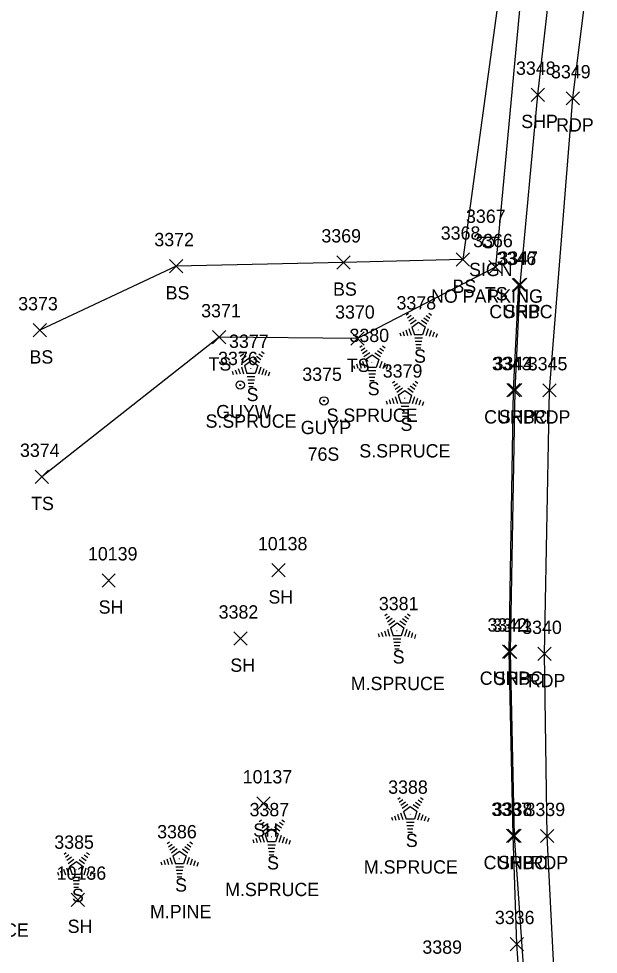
# Model space of a CAD drawing. Extents: x 1769141 to 1770911, y 735471 to 741449.
# Drawn here: x 1770375.7 to 1770462.7, y 737822.4 to 737963 of the extents above; entities that cross this region are included whole.
import ezdxf

# ---------------------------------------------------------------- set-up
doc = ezdxf.new("R2010")
doc.units = 0
for name, color, linetype in [('L_A', 7, 'Continuous'), ('L_C', 7, 'Continuous'), ('L_I', 7, 'Continuous'), ('L_TIC', 7, 'Continuous'), ('LELB', 7, 'Continuous'), ('LTC', 7, 'Continuous'), ('P_A', 7, 'Continuous'), ('P_I', 7, 'Continuous'), ('P_TIC', 7, 'Continuous'), ('PET', 7, 'Continuous'), ('PSP', 7, 'Continuous'), ('R_A', 7, 'Continuous'), ('R_I', 7, 'Continuous'), ('R_TIC', 7, 'Continuous'), ('RC', 7, 'Continuous'), ('S_A', 7, 'Continuous'), ('S_C', 7, 'Continuous'), ('S_I', 7, 'Continuous'), ('SSGN', 7, 'Continuous'), ('U_A', 7, 'Continuous'), ('U_C', 7, 'Continuous'), ('U_I', 7, 'Continuous'), ('UPGW', 7, 'Continuous')]:
    doc.layers.add(name, color=color, linetype=linetype)

msp = doc.modelspace()

# ---------------------------------------------------------------- linework, layer by layer
at = {"layer": 'L_TIC'}
for points in [[(1770441.38, 737925.78), (1770443.38, 737927.78)], [(1770443.38, 737925.78), (1770441.38, 737927.78)], [(1770398.32, 737924.8), (1770400.32, 737926.8)], [(1770400.32, 737924.8), (1770398.32, 737926.8)], [(1770423.46, 737925.36), (1770425.46, 737927.36)], [(1770425.46, 737925.36), (1770423.46, 737927.36)], [(1770446.31, 737924.65), (1770448.31, 737926.65)], [(1770448.31, 737924.65), (1770446.31, 737926.65)], [(1770377.87, 737915.16), (1770379.87, 737917.16)], [(1770379.87, 737915.16), (1770377.87, 737917.16)], [(1770404.79, 737914.11), (1770406.79, 737916.11)], [(1770406.79, 737914.11), (1770404.79, 737916.11)], [(1770425.56, 737913.91), (1770427.56, 737915.91)], [(1770427.56, 737913.91), (1770425.56, 737915.91)], [(1770378.14, 737893.14), (1770380.14, 737895.14)], [(1770380.14, 737893.14), (1770378.14, 737895.14)], [(1770413.71, 737879.1), (1770415.71, 737881.1)], [(1770415.71, 737879.1), (1770413.71, 737881.1)], [(1770388.2, 737877.58), (1770390.2, 737879.58)], [(1770390.2, 737877.58), (1770388.2, 737879.58)], [(1770407.98, 737868.84), (1770409.98, 737870.84)], [(1770409.98, 737868.84), (1770407.98, 737870.84)], [(1770411.44, 737844.07), (1770413.44, 737846.07)], [(1770413.44, 737844.07), (1770411.44, 737846.07)], [(1770383.55, 737829.6), (1770385.55, 737831.6)], [(1770385.55, 737829.6), (1770383.55, 737831.6)], [(1770449.52, 737822.93), (1770451.52, 737824.93)], [(1770451.52, 737822.93), (1770449.52, 737824.93)]]:
    msp.add_lwpolyline(points, dxfattribs=at)
at = {"layer": 'LELB'}
for points in [[(1770453.56, 738018.99), (1770448.11, 737968.65), (1770442.38, 737926.78), (1770424.46, 737926.36), (1770399.32, 737925.8), (1770378.87, 737916.16)], [(1770457.5, 738018.1), (1770451.26, 737968.12), (1770447.31, 737925.65), (1770426.56, 737914.91), (1770405.79, 737915.11), (1770379.14, 737894.14)], [(1770452.13, 737801.86), (1770450.52, 737823.93)]]:
    msp.add_lwpolyline(points, dxfattribs=at)
at = {"layer": 'LTC'}
for p, q in [((1770433.88, 737918.5), (1770434.24, 737918.76)), ((1770434.09, 737918.04), (1770434.62, 737918.42)), ((1770434.3, 737917.57), (1770435.01, 737918.08)), ((1770436.54, 737918.05), (1770437.22, 737917.55)), ((1770436.91, 737918.4), (1770437.46, 737918)), ((1770437.28, 737918.74), (1770437.7, 737918.44)), ((1770434.28, 737916.43), (1770434.61, 737915.41)), ((1770434.51, 737917.11), (1770435.39, 737917.74)), ((1770434.74, 737916.65), (1770435.75, 737917.39)), ((1770434.74, 737916.65), (1770435.12, 737915.46)), ((1770435.75, 737917.39), (1770436.75, 737916.66)), ((1770436.17, 737917.7), (1770436.98, 737917.11)), ((1770436.75, 737916.66), (1770436.35, 737915.46)), ((1770437.18, 737916.39), (1770436.85, 737915.35)), ((1770432.92, 737915.78), (1770433.07, 737915.31)), ((1770433.37, 737916), (1770433.58, 737915.35)), ((1770433.83, 737916.22), (1770434.1, 737915.38)), ((1770436.35, 737915.46), (1770435.12, 737915.46)), ((1770437.63, 737916.14), (1770437.34, 737915.25)), ((1770438.07, 737915.89), (1770437.84, 737915.16)), ((1770438.52, 737915.64), (1770438.33, 737915.06)), ((1770426.92, 737913.61), (1770427.27, 737913.86)), ((1770430.31, 737913.85), (1770430.73, 737913.54)), ((1770436.32, 737914.96), (1770435.17, 737914.96)), ((1770436.23, 737914.46), (1770435.24, 737914.46)), ((1770436.15, 737913.96), (1770435.32, 737913.96)), ((1770408.73, 737912.73), (1770409.09, 737912.98)), ((1770408.94, 737912.26), (1770409.47, 737912.64)), ((1770409.15, 737911.79), (1770409.85, 737912.31)), ((1770411.39, 737912.27), (1770412.07, 737911.78)), ((1770411.76, 737912.62), (1770412.31, 737912.22)), ((1770412.13, 737912.97), (1770412.55, 737912.66)), ((1770427.13, 737913.14), (1770427.65, 737913.52)), ((1770427.34, 737912.67), (1770428.04, 737913.19)), ((1770427.54, 737912.21), (1770428.42, 737912.85)), ((1770427.77, 737911.75), (1770428.78, 737912.49)), ((1770428.78, 737912.49), (1770429.78, 737911.76)), ((1770429.2, 737912.8), (1770430.01, 737912.21)), ((1770429.57, 737913.15), (1770430.25, 737912.66)), ((1770429.94, 737913.5), (1770430.49, 737913.1)), ((1770436.07, 737913.46), (1770435.39, 737913.46)), ((1770409.36, 737911.33), (1770410.24, 737911.97)), ((1770409.58, 737910.87), (1770410.6, 737911.61)), ((1770409.58, 737910.87), (1770409.97, 737909.68)), ((1770410.6, 737911.61), (1770411.59, 737910.88)), ((1770411.02, 737911.92), (1770411.83, 737911.33)), ((1770411.59, 737910.88), (1770411.2, 737909.68)), ((1770425.95, 737910.89), (1770426.1, 737910.42)), ((1770426.4, 737911.1), (1770426.62, 737910.45)), ((1770426.86, 737911.32), (1770427.13, 737910.48)), ((1770427.31, 737911.53), (1770427.65, 737910.52)), ((1770427.77, 737911.75), (1770428.16, 737910.56)), ((1770429.78, 737911.76), (1770429.39, 737910.56)), ((1770430.22, 737911.49), (1770429.88, 737910.45)), ((1770430.66, 737911.24), (1770430.37, 737910.36)), ((1770431.1, 737910.99), (1770430.87, 737910.26)), ((1770407.76, 737910), (1770407.92, 737909.54)), ((1770408.22, 737910.22), (1770408.43, 737909.57)), ((1770408.67, 737910.44), (1770408.95, 737909.6)), ((1770409.13, 737910.65), (1770409.46, 737909.63)), ((1770411.2, 737909.68), (1770409.97, 737909.68)), ((1770412.03, 737910.61), (1770411.69, 737909.57)), ((1770412.48, 737910.36), (1770412.19, 737909.48)), ((1770412.92, 737910.11), (1770412.68, 737909.38)), ((1770413.36, 737909.86), (1770413.18, 737909.29)), ((1770429.39, 737910.56), (1770428.16, 737910.56)), ((1770429.35, 737910.06), (1770428.2, 737910.06)), ((1770429.26, 737909.56), (1770428.28, 737909.56)), ((1770431.55, 737910.74), (1770431.36, 737910.17)), ((1770411.16, 737909.18), (1770410.02, 737909.18)), ((1770411.08, 737908.68), (1770410.09, 737908.68)), ((1770411, 737908.18), (1770410.16, 737908.18)), ((1770429.18, 737909.06), (1770428.35, 737909.06)), ((1770429.1, 737908.56), (1770428.42, 737908.56)), ((1770431.84, 737908.26), (1770432.19, 737908.52)), ((1770432.04, 737907.8), (1770432.57, 737908.18)), ((1770434.86, 737908.15), (1770435.41, 737907.75)), ((1770435.23, 737908.5), (1770435.65, 737908.2)), ((1770410.91, 737907.68), (1770410.24, 737907.68)), ((1770432.25, 737907.33), (1770432.96, 737907.84)), ((1770432.46, 737906.86), (1770433.34, 737907.5)), ((1770432.69, 737906.41), (1770433.7, 737907.14)), ((1770433.7, 737907.14), (1770434.7, 737906.42)), ((1770434.12, 737907.46), (1770434.93, 737906.87)), ((1770434.49, 737907.81), (1770435.17, 737907.31)), ((1770430.87, 737905.54), (1770431.02, 737905.07)), ((1770431.32, 737905.76), (1770431.53, 737905.11)), ((1770431.78, 737905.97), (1770432.05, 737905.14)), ((1770432.23, 737906.19), (1770432.56, 737905.17)), ((1770432.69, 737906.41), (1770433.08, 737905.22)), ((1770434.31, 737905.22), (1770433.08, 737905.22)), ((1770434.7, 737906.42), (1770434.31, 737905.22)), ((1770435.13, 737906.15), (1770434.8, 737905.11)), ((1770435.58, 737905.9), (1770435.29, 737905.01)), ((1770436.02, 737905.65), (1770435.79, 737904.92)), ((1770436.47, 737905.4), (1770436.28, 737904.82)), ((1770434.27, 737904.72), (1770433.12, 737904.72)), ((1770434.18, 737904.22), (1770433.2, 737904.22)), ((1770434.1, 737903.72), (1770433.27, 737903.72)), ((1770434.02, 737903.22), (1770433.34, 737903.22)), ((1770430.67, 737873.3), (1770431.02, 737873.56)), ((1770430.87, 737872.83), (1770431.4, 737873.22)), ((1770431.08, 737872.37), (1770431.79, 737872.88)), ((1770433.32, 737872.84), (1770434, 737872.35)), ((1770433.69, 737873.19), (1770434.24, 737872.79)), ((1770434.06, 737873.54), (1770434.48, 737873.23)), ((1770431.29, 737871.9), (1770432.17, 737872.54)), ((1770431.52, 737871.45), (1770432.53, 737872.18)), ((1770431.52, 737871.45), (1770431.91, 737870.25)), ((1770432.53, 737872.18), (1770433.53, 737871.46)), ((1770432.95, 737872.49), (1770433.76, 737871.91)), ((1770433.53, 737871.46), (1770433.14, 737870.25)), ((1770429.7, 737870.58), (1770429.85, 737870.11)), ((1770430.15, 737870.79), (1770430.36, 737870.14)), ((1770430.61, 737871.01), (1770430.88, 737870.18)), ((1770431.06, 737871.23), (1770431.39, 737870.21)), ((1770433.14, 737870.25), (1770431.91, 737870.25)), ((1770433.96, 737871.19), (1770433.63, 737870.15)), ((1770434.41, 737870.93), (1770434.12, 737870.05)), ((1770434.85, 737870.68), (1770434.62, 737869.96)), ((1770435.3, 737870.43), (1770435.11, 737869.86)), ((1770433.1, 737869.75), (1770431.95, 737869.75)), ((1770433.01, 737869.25), (1770432.03, 737869.25)), ((1770432.93, 737868.75), (1770432.1, 737868.75)), ((1770432.85, 737868.25), (1770432.17, 737868.25)), ((1770432.64, 737845.72), (1770432.99, 737845.98)), ((1770432.85, 737845.26), (1770433.38, 737845.64)), ((1770433.06, 737844.79), (1770433.76, 737845.3)), ((1770433.27, 737844.33), (1770434.15, 737844.97)), ((1770434.92, 737844.92), (1770435.73, 737844.33)), ((1770435.3, 737845.27), (1770435.97, 737844.77)), ((1770435.67, 737845.62), (1770436.22, 737845.22)), ((1770436.04, 737845.97), (1770436.46, 737845.66)), ((1770432.58, 737843.44), (1770432.85, 737842.6)), ((1770433.04, 737843.65), (1770433.37, 737842.63)), ((1770433.49, 737843.87), (1770434.5, 737844.61)), ((1770433.49, 737843.87), (1770433.88, 737842.68)), ((1770434.5, 737844.61), (1770435.5, 737843.88)), ((1770435.5, 737843.88), (1770435.11, 737842.68)), ((1770435.94, 737843.61), (1770435.6, 737842.57)), ((1770436.38, 737843.36), (1770436.1, 737842.48)), ((1770411.81, 737842.35), (1770412.17, 737842.61)), ((1770412.02, 737841.88), (1770412.55, 737842.27)), ((1770412.23, 737841.42), (1770412.93, 737841.93)), ((1770414.47, 737841.89), (1770415.15, 737841.4)), ((1770414.84, 737842.24), (1770415.39, 737841.84)), ((1770415.21, 737842.59), (1770415.63, 737842.28)), ((1770431.67, 737843), (1770431.82, 737842.54)), ((1770432.13, 737843.22), (1770432.34, 737842.57)), ((1770435.11, 737842.68), (1770433.88, 737842.68)), ((1770435.07, 737842.18), (1770433.93, 737842.18)), ((1770436.83, 737843.11), (1770436.59, 737842.38)), ((1770437.27, 737842.86), (1770437.09, 737842.29)), ((1770412.44, 737840.95), (1770413.32, 737841.59)), ((1770412.66, 737840.5), (1770413.68, 737841.23)), ((1770412.66, 737840.5), (1770413.05, 737839.3)), ((1770413.68, 737841.23), (1770414.67, 737840.51)), ((1770414.1, 737841.54), (1770414.91, 737840.96)), ((1770414.67, 737840.51), (1770414.28, 737839.3)), ((1770434.99, 737841.68), (1770434, 737841.68)), ((1770434.9, 737841.18), (1770434.07, 737841.18)), ((1770434.82, 737840.68), (1770434.15, 737840.68)), ((1770397.99, 737839.03), (1770398.34, 737839.29)), ((1770401.39, 737839.27), (1770401.8, 737838.97)), ((1770410.84, 737839.63), (1770411, 737839.16)), ((1770411.3, 737839.84), (1770411.51, 737839.19)), ((1770411.75, 737840.06), (1770412.03, 737839.23)), ((1770412.21, 737840.28), (1770412.54, 737839.26)), ((1770414.28, 737839.3), (1770413.05, 737839.3)), ((1770415.11, 737840.24), (1770414.77, 737839.2)), ((1770415.55, 737839.99), (1770415.27, 737839.1)), ((1770416, 737839.74), (1770415.76, 737839.01)), ((1770416.44, 737839.48), (1770416.26, 737838.91)), ((1770382.49, 737837.45), (1770382.84, 737837.71)), ((1770385.89, 737837.7), (1770386.3, 737837.39)), ((1770398.2, 737838.56), (1770398.73, 737838.95)), ((1770398.41, 737838.1), (1770399.11, 737838.61)), ((1770398.62, 737837.63), (1770399.49, 737838.27)), ((1770398.84, 737837.18), (1770399.85, 737837.91)), ((1770399.85, 737837.91), (1770400.85, 737837.19)), ((1770400.27, 737838.23), (1770401.08, 737837.64)), ((1770400.64, 737838.57), (1770401.32, 737838.08)), ((1770401.01, 737838.92), (1770401.56, 737838.52)), ((1770414.24, 737838.8), (1770413.1, 737838.8)), ((1770414.16, 737838.3), (1770413.17, 737838.3)), ((1770414.08, 737837.8), (1770413.24, 737837.8)), ((1770382.7, 737836.99), (1770383.23, 737837.37)), ((1770382.91, 737836.52), (1770383.61, 737837.03)), ((1770383.12, 737836.06), (1770383.99, 737836.7)), ((1770383.34, 737835.6), (1770384.35, 737836.34)), ((1770384.35, 737836.34), (1770385.35, 737835.61)), ((1770384.77, 737836.65), (1770385.58, 737836.06)), ((1770385.14, 737837), (1770385.82, 737836.5)), ((1770385.51, 737837.35), (1770386.06, 737836.95)), ((1770397.02, 737836.31), (1770397.17, 737835.84)), ((1770397.47, 737836.53), (1770397.69, 737835.87)), ((1770397.93, 737836.74), (1770398.2, 737835.91)), ((1770398.39, 737836.96), (1770398.72, 737835.94)), ((1770398.84, 737837.18), (1770399.23, 737835.98)), ((1770400.85, 737837.19), (1770400.46, 737835.98)), ((1770401.29, 737836.92), (1770400.95, 737835.88)), ((1770401.73, 737836.67), (1770401.44, 737835.78)), ((1770402.18, 737836.42), (1770401.94, 737835.69)), ((1770413.99, 737837.3), (1770413.32, 737837.3)), ((1770381.98, 737834.95), (1770382.19, 737834.3)), ((1770382.43, 737835.17), (1770382.7, 737834.33)), ((1770382.89, 737835.38), (1770383.22, 737834.36)), ((1770383.34, 737835.6), (1770383.73, 737834.41)), ((1770385.35, 737835.61), (1770384.96, 737834.41)), ((1770385.79, 737835.34), (1770385.45, 737834.3)), ((1770386.23, 737835.09), (1770385.94, 737834.21)), ((1770386.68, 737834.84), (1770386.44, 737834.11)), ((1770400.46, 737835.98), (1770399.23, 737835.98)), ((1770400.42, 737835.48), (1770399.27, 737835.48)), ((1770400.34, 737834.98), (1770399.35, 737834.98)), ((1770402.62, 737836.17), (1770402.43, 737835.59)), ((1770381.52, 737834.73), (1770381.67, 737834.27)), ((1770384.96, 737834.41), (1770383.73, 737834.41)), ((1770384.92, 737833.91), (1770383.78, 737833.91)), ((1770387.12, 737834.59), (1770386.93, 737834.02)), ((1770400.25, 737834.48), (1770399.42, 737834.48)), ((1770400.17, 737833.98), (1770399.49, 737833.98)), ((1770384.84, 737833.41), (1770383.85, 737833.41)), ((1770384.75, 737832.91), (1770383.92, 737832.91)), ((1770384.67, 737832.41), (1770383.99, 737832.41))]:
    msp.add_line(p, q, dxfattribs=at)
at = {"layer": 'P_TIC'}
for points in [[(1770452.64, 737950.55), (1770454.64, 737952.55)], [(1770454.64, 737950.55), (1770452.64, 737952.55)], [(1770457.91, 737950.02), (1770459.91, 737952.02)], [(1770459.91, 737950.02), (1770457.91, 737952.02)], [(1770450, 737922.01), (1770452, 737924.01)], [(1770452, 737922.01), (1770450, 737924.01)], [(1770449.27, 737906.19), (1770451.27, 737908.19)], [(1770451.27, 737906.19), (1770449.27, 737908.19)], [(1770454.41, 737906.14), (1770456.41, 737908.14)], [(1770456.41, 737906.14), (1770454.41, 737908.14)], [(1770448.53, 737866.85), (1770450.53, 737868.85)], [(1770450.53, 737866.85), (1770448.53, 737868.85)], [(1770453.66, 737866.53), (1770455.66, 737868.53)], [(1770455.66, 737866.53), (1770453.66, 737868.53)], [(1770449.15, 737839.19), (1770451.15, 737841.19)], [(1770451.15, 737839.19), (1770449.15, 737841.19)], [(1770454.08, 737839.17), (1770456.08, 737841.17)], [(1770456.08, 737839.17), (1770454.08, 737841.17)]]:
    msp.add_lwpolyline(points, dxfattribs=at)
at = {"layer": 'PET'}
msp.add_lwpolyline([(1770457.07, 737800.74), (1770455.08, 737840.17), (1770454.66, 737867.53), (1770455.41, 737907.14), (1770458.91, 737951.02), (1770462.77, 737982), (1770468.01, 738016.71), (1770472.65, 738047.02), (1770479.32, 738087.24), (1770484.16, 738118.08), (1770491.23, 738160.7), (1770498.35, 738202.33), (1770505.32, 738243.58)], dxfattribs=at)
at = {"layer": 'PSP'}
msp.add_lwpolyline([(1770452.89, 737800.45), (1770450.15, 737840.19), (1770449.53, 737867.85), (1770450.27, 737907.19), (1770451, 737923.01), (1770453.64, 737951.55), (1770457.18, 737982.52), (1770462.08, 738017.26), (1770466.97, 738048.11), (1770473.48, 738088.83), (1770478.08, 738119.4), (1770485.23, 738161.48), (1770492.13, 738203.4), (1770499.17, 738244.91)], dxfattribs=at)
at = {"layer": 'R_TIC'}
for points in [[(1770449.79, 737921.97), (1770451.79, 737923.97)], [(1770451.79, 737921.97), (1770449.79, 737923.97)], [(1770449.02, 737906.15), (1770451.02, 737908.15)], [(1770451.02, 737906.15), (1770449.02, 737908.15)], [(1770448.36, 737866.89), (1770450.36, 737868.89)], [(1770450.36, 737866.89), (1770448.36, 737868.89)], [(1770448.93, 737839.18), (1770450.93, 737841.18)], [(1770450.93, 737839.18), (1770448.93, 737841.18)], [(1770449.52, 737822.93), (1770451.52, 737824.93)], [(1770451.52, 737822.93), (1770449.52, 737824.93)]]:
    msp.add_lwpolyline(points, dxfattribs=at)
at = {"layer": 'RC'}
msp.add_lwpolyline([(1770450.52, 737823.93), (1770449.93, 737840.18), (1770449.36, 737867.89), (1770450.02, 737907.15), (1770450.79, 737922.97)], dxfattribs=at)
at = {"layer": 'SSGN'}
for p, q in [((1770444.55, 737930.15), (1770447.88, 737930.15)), ((1770446.2, 737929.32), (1770446.2, 737929.32))]:
    msp.add_line(p, q, dxfattribs=at)
msp.add_circle((1770446.2, 737929.32), 0.833, dxfattribs=at)
at = {"layer": 'UPGW'}
for centre, radius in [((1770408.96, 737907.94), 0.625), ((1770408.96, 737907.94), 0.0833), ((1770421.54, 737905.56), 0.625), ((1770421.54, 737905.56), 0.0833)]:
    msp.add_circle(centre, radius, dxfattribs=at)

# ---------------------------------------------------------------- texts
at = {"layer": 'L_A'}
for s, p in [('BS', (1770440.83, 737921.78)), ('BS', (1770397.76, 737920.8)), ('BS', (1770422.9, 737921.36)), ('TS', (1770445.72, 737920.65)), ('BS', (1770377.31, 737911.16)), ('S', (1770435.07, 737911.29)), ('TS', (1770404.2, 737910.11)), ('TS', (1770424.97, 737909.91)), ('S', (1770428.11, 737906.4)), ('S', (1770409.92, 737905.52)), ('S', (1770433.03, 737901.05)), ('TS', (1770377.55, 737889.14)), ('SH', (1770413.2, 737875.1)), ('SH', (1770387.69, 737873.58)), ('S', (1770431.86, 737866.09)), ('SH', (1770407.47, 737864.84)), ('SH', (1770410.92, 737840.07)), ('S', (1770433.83, 737838.52)), ('S', (1770413, 737835.14)), ('S', (1770399.18, 737831.82)), ('S', (1770383.68, 737830.25)), ('SH', (1770383.04, 737825.6))]:
    msp.add_text(s, height=2, dxfattribs=at).set_placement(p)
at = {"layer": 'L_C'}
for s, p in [('S.SPRUCE', (1770421.93, 737902.4)), ('S.SPRUCE', (1770403.75, 737901.52)), ('S.SPRUCE', (1770426.85, 737897.05)), ('M.SPRUCE', (1770425.56, 737862.09)), ('M.SPRUCE', (1770427.53, 737834.52)), ('M.SPRUCE', (1770406.7, 737831.14)), ('M.PINE', (1770395.4, 737827.82)), ('S.SPRUCE', (1770363.53, 737825.04))]:
    msp.add_text(s, height=2, dxfattribs=at).set_placement(p)
at = {"layer": 'L_I'}
for s, p in [('3372', (1770396.06, 737928.8)), ('3369', (1770421.15, 737929.36)), ('3368', (1770439.08, 737929.78)), ('3366', (1770443.95, 737928.65)), ('3373', (1770375.61, 737919.16)), ('3378', (1770432.43, 737919.29)), ('3371', (1770403.09, 737918.11)), ('3370', (1770423.21, 737917.91)), ('3380', (1770425.37, 737914.4)), ('3377', (1770407.28, 737913.52)), ('3379', (1770430.37, 737909.05)), ('3374', (1770375.88, 737897.14)), ('10138', (1770411.61, 737883.1)), ('10139', (1770386.09, 737881.58)), ('3381', (1770429.78, 737874.09)), ('3382', (1770405.72, 737872.84)), ('10137', (1770409.33, 737848.07)), ('3388', (1770431.18, 737846.52)), ('3387', (1770410.36, 737843.14)), ('3386', (1770396.48, 737839.82)), ('3385', (1770381.03, 737838.25)), ('10136', (1770381.39, 737833.6)), ('3336', (1770447.21, 737826.93)), ('3389', (1770436.32, 737822.48))]:
    msp.add_text(s, height=2, dxfattribs=at).set_placement(p)
at = {"layer": 'LTC'}
for p in [(1770435.63, 737916.4), (1770428.66, 737911.5), (1770410.48, 737910.62), (1770433.58, 737906.16), (1770432.41, 737871.19), (1770434.39, 737843.62), (1770413.56, 737840.24), (1770399.73, 737836.93), (1770384.23, 737835.35)]:
    msp.add_text('.', height=1.04, rotation=270, dxfattribs=at).set_placement(p)
at = {"layer": 'P_A'}
for s, p in [('SHP', (1770451.17, 737946.55)), ('RDP', (1770456.4, 737946.02)), ('SHP', (1770448.54, 737918.01)), ('SHP', (1770447.8, 737902.19)), ('RDP', (1770452.9, 737902.14)), ('SHP', (1770447.07, 737862.85)), ('RDP', (1770452.15, 737862.53)), ('SHP', (1770447.68, 737835.19)), ('RDP', (1770452.57, 737835.17))]:
    msp.add_text(s, height=2, dxfattribs=at).set_placement(p)
at = {"layer": 'P_I'}
for s, p in [('3348', (1770450.38, 737954.55)), ('3349', (1770455.64, 737954.02)), ('3347', (1770447.74, 737926.01)), ('3344', (1770447.01, 737910.19)), ('3345', (1770452.15, 737910.14)), ('3341', (1770446.84, 737870.85)), ('3340', (1770451.31, 737870.53)), ('3338', (1770446.89, 737843.19)), ('3339', (1770451.81, 737843.17))]:
    msp.add_text(s, height=2, dxfattribs=at).set_placement(p)
at = {"layer": 'R_A'}
for p in [(1770446.37, 737917.97), (1770445.6, 737902.15), (1770444.94, 737862.89), (1770445.51, 737835.18)]:
    msp.add_text('CURBC', height=2, dxfattribs=at).set_placement(p)
at = {"layer": 'R_I'}
for s, p in [('3346', (1770447.47, 737925.97)), ('3343', (1770446.76, 737910.15)), ('3342', (1770446.1, 737870.89)), ('3337', (1770446.67, 737843.18)), ('3336', (1770447.21, 737826.93))]:
    msp.add_text(s, height=2, dxfattribs=at).set_placement(p)
at = {"layer": 'S_A'}
msp.add_text('SIGN', height=2, dxfattribs=at).set_placement((1770443.33, 737924.3))
at = {"layer": 'S_C'}
msp.add_text('NO PARKING', height=2, dxfattribs=at).set_placement((1770437.62, 737920.3))
at = {"layer": 'S_I'}
msp.add_text('3367', height=2, dxfattribs=at).set_placement((1770442.87, 737932.3))
at = {"layer": 'U_A'}
for s, p in [('GUYW', (1770405.35, 737902.94)), ('GUYP', (1770418.05, 737900.56))]:
    msp.add_text(s, height=2, dxfattribs=at).set_placement(p)
at = {"layer": 'U_C'}
msp.add_text('76S', height=2, dxfattribs=at).set_placement((1770419.08, 737896.56))
at = {"layer": 'U_I'}
for s, p in [('3376', (1770405.64, 737910.94)), ('3375', (1770418.28, 737908.56))]:
    msp.add_text(s, height=2, dxfattribs=at).set_placement(p)

doc.saveas('drawing.dxf')
